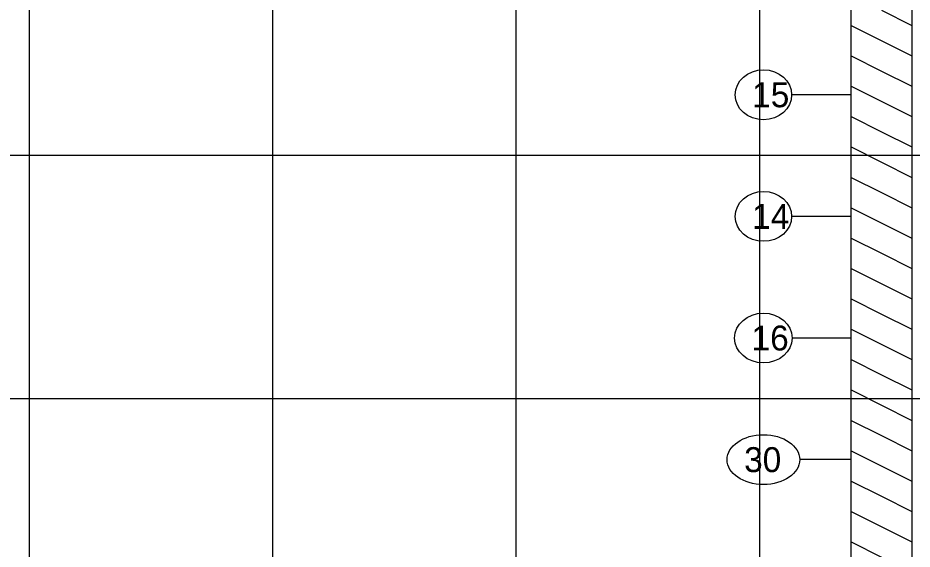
# Model space of a CAD drawing. Extents: x 278618 to 280654, y 171155 to 171855.
# Drawn here: x 280043.65 to 280080.38, y 171201.56 to 171223.4 of the extents above; entities that cross this region are included whole.
import ezdxf

# ---------------------------------------------------------------- set-up
doc = ezdxf.new("R2010")
doc.units = 0
for name, color, linetype in [('Prop Road Sect_ Boring - Material (Outline)', 7, 'Continuous'), ('Prop Road Sect_ Boring - Peripheral (SPT Oval + Leader)', 7, 'Continuous'), ('Prop Road Sect_ Boring - Peripheral (SPT Tx)', 7, 'Continuous'), ('Prop Strc Sect_ Grid - minor', 7, 'Continuous')]:
    doc.layers.add(name, color=color, linetype=linetype)

msp = doc.modelspace()

# ---------------------------------------------------------------- linework, layer by layer
at = {"layer": 'Prop Road Sect_ Boring - Material (Outline)'}
for p, q in [((280079.123, 171223.715), (280080.372, 171223.091)), ((280079.123, 171223.715), (280080.372, 171223.091)), ((280077.875, 171223.091), (280080.372, 171221.842)), ((280077.875, 171223.091), (280080.372, 171221.842)), ((280077.875, 171223.091), (280080.372, 171221.842)), ((280077.875, 171223.091), (280080.372, 171221.842)), ((280080.372, 171223.091), (280080.375, 171223.09)), ((280080.372, 171223.091), (280080.375, 171223.09)), ((280080.372, 171223.091), (280080.375, 171223.09)), ((280080.372, 171223.091), (280080.375, 171223.09)), ((280077.875, 171221.842), (280079.123, 171221.218)), ((280077.875, 171221.842), (280079.123, 171221.218)), ((280080.372, 171221.842), (280080.375, 171221.841)), ((280080.372, 171221.842), (280080.375, 171221.841)), ((280079.123, 171221.218), (280080.372, 171220.594)), ((280079.123, 171221.218), (280080.372, 171220.594)), ((280077.875, 171220.594), (280080.372, 171219.345)), ((280077.875, 171220.594), (280080.372, 171219.345)), ((280077.875, 171220.594), (280080.372, 171219.345)), ((280077.875, 171220.594), (280080.372, 171219.345)), ((280080.372, 171220.594), (280080.375, 171220.592)), ((280080.372, 171220.594), (280080.375, 171220.592)), ((280080.372, 171220.594), (280080.375, 171220.592)), ((280080.372, 171220.594), (280080.375, 171220.592)), ((280077.875, 171219.345), (280079.123, 171218.72)), ((280077.875, 171219.345), (280079.123, 171218.72)), ((280080.372, 171219.345), (280080.375, 171219.344)), ((280080.372, 171219.345), (280080.375, 171219.344)), ((280079.123, 171218.72), (280080.372, 171218.096)), ((280079.123, 171218.72), (280080.372, 171218.096)), ((280077.875, 171218.096), (280080.372, 171216.847)), ((280077.875, 171218.096), (280080.372, 171216.847)), ((280077.875, 171218.096), (280080.372, 171216.847)), ((280077.875, 171218.096), (280080.372, 171216.847)), ((280080.372, 171218.096), (280080.375, 171218.095)), ((280080.372, 171218.096), (280080.375, 171218.095)), ((280080.372, 171218.096), (280080.375, 171218.095)), ((280080.372, 171218.096), (280080.375, 171218.095)), ((280077.875, 171216.847), (280079.123, 171216.223)), ((280077.875, 171216.847), (280079.123, 171216.223)), ((280080.372, 171216.847), (280080.375, 171216.846)), ((280080.372, 171216.847), (280080.375, 171216.846)), ((280079.123, 171216.223), (280080.372, 171215.599)), ((280079.123, 171216.223), (280080.372, 171215.599)), ((280077.875, 171215.599), (280080.372, 171214.35)), ((280077.875, 171215.599), (280080.372, 171214.35)), ((280077.875, 171215.599), (280080.372, 171214.35)), ((280077.875, 171215.599), (280080.372, 171214.35)), ((280080.372, 171215.599), (280080.375, 171215.597)), ((280080.372, 171215.599), (280080.375, 171215.597)), ((280080.372, 171215.599), (280080.375, 171215.597)), ((280080.372, 171215.599), (280080.375, 171215.597)), ((280077.875, 171214.35), (280079.123, 171213.725)), ((280077.875, 171214.35), (280079.123, 171213.725)), ((280080.372, 171214.35), (280080.375, 171214.349)), ((280080.372, 171214.35), (280080.375, 171214.349)), ((280079.123, 171213.725), (280080.372, 171213.101)), ((280079.123, 171213.725), (280080.372, 171213.101)), ((280077.875, 171213.101), (280080.372, 171211.852)), ((280077.875, 171213.101), (280080.372, 171211.852)), ((280077.875, 171213.101), (280080.372, 171211.852)), ((280077.875, 171213.101), (280080.372, 171211.852)), ((280080.372, 171213.101), (280080.375, 171213.1)), ((280080.372, 171213.101), (280080.375, 171213.1)), ((280080.372, 171213.101), (280080.375, 171213.1)), ((280080.372, 171213.101), (280080.375, 171213.1)), ((280077.875, 171211.852), (280079.123, 171211.228)), ((280077.875, 171211.852), (280079.123, 171211.228)), ((280080.372, 171211.852), (280080.375, 171211.851)), ((280080.372, 171211.852), (280080.375, 171211.851)), ((280079.123, 171211.228), (280080.372, 171210.603)), ((280079.123, 171211.228), (280080.372, 171210.603)), ((280077.875, 171210.603), (280080.372, 171209.355)), ((280077.875, 171210.603), (280080.372, 171209.355)), ((280077.875, 171210.603), (280080.372, 171209.355)), ((280077.875, 171210.603), (280080.372, 171209.355)), ((280080.372, 171210.603), (280080.375, 171210.602)), ((280080.372, 171210.603), (280080.375, 171210.602)), ((280080.372, 171210.603), (280080.375, 171210.602)), ((280080.372, 171210.603), (280080.375, 171210.602)), ((280077.875, 171209.355), (280079.123, 171208.73)), ((280077.875, 171209.355), (280079.123, 171208.73)), ((280080.372, 171209.355), (280080.375, 171209.353)), ((280080.372, 171209.355), (280080.375, 171209.353)), ((280079.123, 171208.73), (280080.372, 171208.106)), ((280079.123, 171208.73), (280080.372, 171208.106)), ((280077.875, 171208.106), (280080.372, 171206.857)), ((280077.875, 171208.106), (280080.372, 171206.857)), ((280077.875, 171208.106), (280080.372, 171206.857)), ((280077.875, 171208.106), (280080.372, 171206.857)), ((280080.372, 171208.106), (280080.375, 171208.105)), ((280080.372, 171208.106), (280080.375, 171208.105)), ((280080.372, 171208.106), (280080.375, 171208.105)), ((280080.372, 171208.106), (280080.375, 171208.105)), ((280077.875, 171206.857), (280079.123, 171206.233)), ((280077.875, 171206.857), (280079.123, 171206.233)), ((280080.372, 171206.857), (280080.375, 171206.856)), ((280080.372, 171206.857), (280080.375, 171206.856)), ((280079.123, 171206.233), (280080.372, 171205.608)), ((280079.123, 171206.233), (280080.372, 171205.608)), ((280077.875, 171205.608), (280080.372, 171204.36)), ((280077.875, 171205.608), (280080.372, 171204.36)), ((280077.875, 171205.608), (280080.372, 171204.36)), ((280077.875, 171205.608), (280080.372, 171204.36)), ((280080.372, 171205.608), (280080.375, 171205.607)), ((280080.372, 171205.608), (280080.375, 171205.607)), ((280080.372, 171205.608), (280080.375, 171205.607)), ((280080.372, 171205.608), (280080.375, 171205.607)), ((280077.875, 171204.36), (280079.123, 171203.735)), ((280077.875, 171204.36), (280079.123, 171203.735)), ((280080.372, 171204.36), (280080.375, 171204.358)), ((280080.372, 171204.36), (280080.375, 171204.358)), ((280079.123, 171203.735), (280080.372, 171203.111)), ((280079.123, 171203.735), (280080.372, 171203.111)), ((280077.875, 171203.111), (280080.372, 171201.862)), ((280077.875, 171203.111), (280080.372, 171201.862)), ((280077.875, 171203.111), (280080.372, 171201.862)), ((280077.875, 171203.111), (280080.372, 171201.862)), ((280080.372, 171203.111), (280080.375, 171203.11)), ((280080.372, 171203.111), (280080.375, 171203.11)), ((280080.372, 171203.111), (280080.375, 171203.11)), ((280080.372, 171203.111), (280080.375, 171203.11)), ((280077.875, 171201.862), (280079.123, 171201.238)), ((280077.875, 171201.862), (280079.123, 171201.238)), ((280080.372, 171201.862), (280080.375, 171201.861)), ((280080.372, 171201.862), (280080.375, 171201.861))]:
    msp.add_line(p, q, dxfattribs=at)
msp.add_lwpolyline([(280077.875, 171251.243), (280080.375, 171251.243), (280080.375, 171196.243), (280077.875, 171196.243)], close=True, dxfattribs=at)
at = {"layer": 'Prop Road Sect_ Boring - Peripheral (SPT Oval + Leader)'}
for p, q in [((280077.875, 171220.243), (280075.435, 171220.243)), ((280077.875, 171215.243), (280075.435, 171215.243)), ((280077.875, 171210.243), (280075.459, 171210.243)), ((280077.875, 171205.243), (280075.766, 171205.243))]:
    msp.add_line(p, q, dxfattribs=at)
for centre, major_axis, ratio in [((280074.275, 171220.243), (1.16, 0), 0.883591), ((280074.275, 171215.243), (1.16, 0), 0.883591), ((280074.275, 171210.243), (1.184, 0), 0.865525), ((280074.275, 171205.243), (1.491, 0), 0.687483)]:
    msp.add_ellipse(centre, major_axis=major_axis, ratio=ratio, dxfattribs=at)
at = {"layer": 'Prop Strc Sect_ Grid - minor'}
for p, q in [((280044.125, 171188.859), (280044.125, 171293.859)), ((280054.125, 171188.859), (280054.125, 171293.859)), ((280064.125, 171188.859), (280064.125, 171293.859)), ((280074.125, 171188.859), (280074.125, 171293.859)), ((280174.125, 171217.743), (280024.125, 171217.743)), ((280174.125, 171207.743), (280024.125, 171207.743))]:
    msp.add_line(p, q, dxfattribs=at)

# ---------------------------------------------------------------- texts
at = {"layer": 'Prop Road Sect_ Boring - Peripheral (SPT Tx)'}
for s, p in [('15', (280073.815, 171219.73)), ('14', (280073.815, 171214.73)), ('16', (280073.79, 171209.73)), ('30', (280073.484, 171204.73))]:
    msp.add_text(s, height=1.025, dxfattribs=at).set_placement(p)

doc.saveas('drawing.dxf')
